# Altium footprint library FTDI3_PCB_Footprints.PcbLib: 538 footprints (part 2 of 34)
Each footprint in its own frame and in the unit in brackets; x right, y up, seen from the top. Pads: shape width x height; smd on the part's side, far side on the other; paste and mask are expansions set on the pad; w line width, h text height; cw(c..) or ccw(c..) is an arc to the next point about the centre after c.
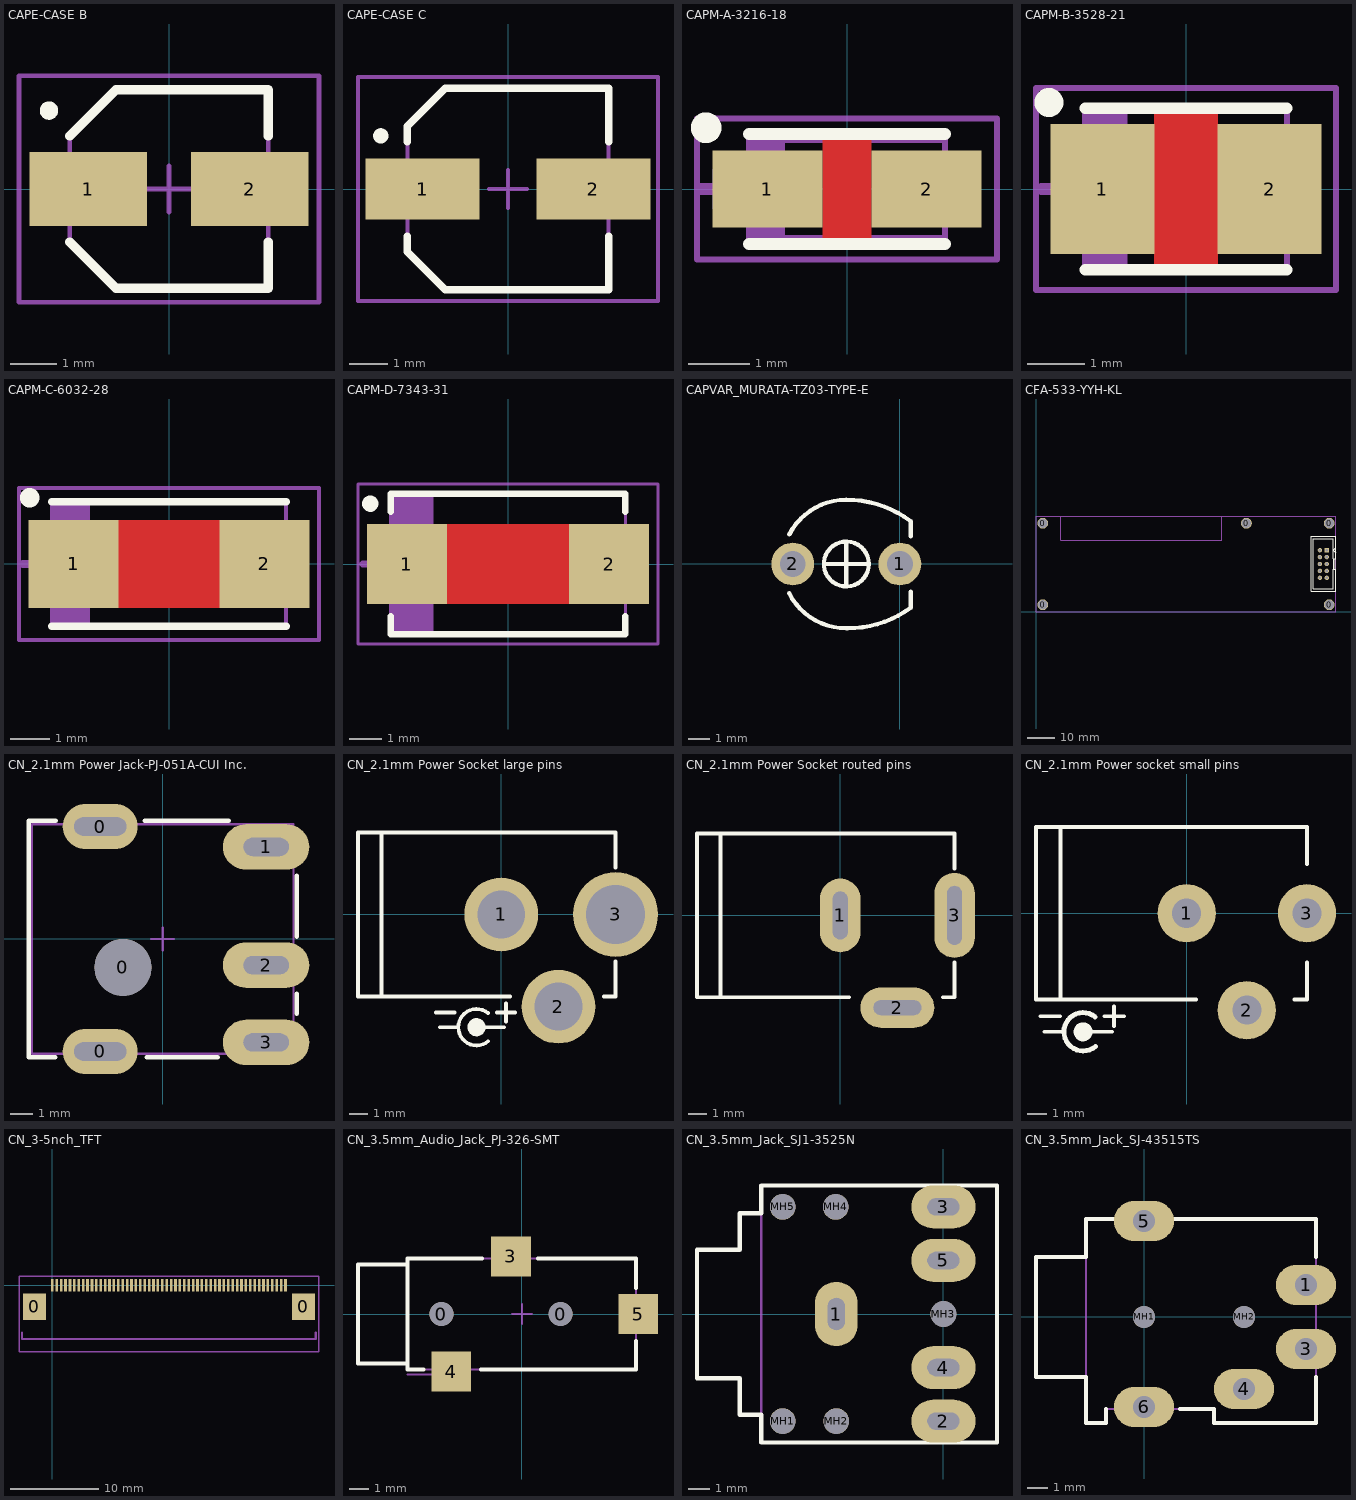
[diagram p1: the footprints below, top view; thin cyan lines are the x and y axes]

## CAPE-CASE B [mm] "Capacitor, aluminium electrolitytic; SMT, Case B"
pads (2):
  rect 2.55x1.6 smd: 1(-1.75,0) 2(1.75,0)
Top Overlay:
  circle w0.2: c-2.6,1.7 r0.1
  lines w0.2: -2.15,-1.15 -1.15,-2.15 2.15,-2.15 2.15,-1.15 ; -2.15,1.15 -1.15,2.15 2.15,2.15 2.15,1.15
M13_Assembly_Info:
  lines w0.1: -2.15,-1.15 -2.15,1.15 -1.15,2.15 2.15,2.15 2.15,-2.15 -1.15,-2.15 -2.15,-1.15
M15_Country_Yard:
  lines w0.1: -0.5,0 0.5,0 ; 0,-0.5 0,0.5 ; -3.25,-2.45 -3.25,2.45 3.25,2.45 3.25,-2.45 -3.25,-2.45
3D body: height 5.4, standoff 0, extent -2.3,-2.15 2.3,2.15

## CAPE-CASE C [mm] "Capacitor, aluminium electrolitytic; SMT, Case C"
pads (2):
  rect 3x1.6 smd: 1(-2.25,0) 2(2.25,0)
Top Overlay:
  circle w0.2: c-3.35,1.4 r0.1
  lines w0.2: -2.65,-1.25 -2.65,-1.65 -1.65,-2.65 2.65,-2.65 2.65,-1.25 ; -2.65,1.25 -2.65,1.65 -1.65,2.65 2.65,2.65 2.65,1.25
M13_Assembly_Info:
  lines w0.1: -2.65,-1.65 -1.65,-2.65 2.65,-2.65 2.65,2.65 -1.65,2.65 -2.65,1.65 -2.65,-1.65
M15_Country_Yard:
  lines w0.1: -0.5,0 0.5,0 ; 0,-0.5 0,0.5 ; -3.95,-2.95 3.95,-2.95 3.95,2.95 -3.95,2.95 -3.95,-2.95
3D body: height 5.41, standoff 0, extent -3,-2.625 2.9,2.675

## CAPM-A-3216-18 [mm] "Capacitor, SMT Tantalum; Body 3.2 x 1.6 mm (LxW typ)"
height 2.2
pads (2):
  rect 1.8x1.25 smd: 1(-1.3,0) 2(1.3,0)
Top Layer:
  pour cut-out: -0.4,0.9 0.4,0.9 0.4,-0.9 -0.4,-0.9
Top Overlay:
  circle w0.3: c-2.3,1 r0.1
  lines w0.2: -1.6,-0.9 1.6,-0.9 ; -1.6,0.9 1.6,0.9
M13_Assembly_Info:
  rectangle: -1.6,-0.8 -1.016,0.8
  lines w0.1: -1.6,-0.8 1.6,-0.8 1.6,0.8 -1.6,0.8 -1.6,-0.8
  lines w0.2: -2.4,0 -1.8,0 ; -2.1,-0.3 -2.1,0.3
M15_Country_Yard:
  lines w0.1: -0.35,0 0.35,0 ; 0,-0.35 0,0.35 ; -2.45,-1.15 2.45,-1.15 2.45,1.15 -2.45,1.15 -2.45,-1.15
3D body: height 1.8, standoff 0, extent -1.025,-0.8 1.6,0.8
3D body: height 1.8, standoff 0, extent -1.6,-0.8 -1.016,0.8

## CAPM-B-3528-21 [mm] "Capacitor, SMT Tantalum; Body 3.5 x 2.8 mm (LxW typ)"
height 2.5
pads (2):
  rect 1.8x2.25 smd: 1(-1.45,0) 2(1.45,0)
Top Layer:
  pour cut-out: -0.55,1.4 0.55,1.4 0.55,-1.4 -0.55,-1.4
Top Overlay:
  circle w0.3: c-2.375,1.5 r0.1
  lines w0.2: -1.75,-1.4 1.75,-1.4 ; -1.75,1.4 1.75,1.4
M13_Assembly_Info:
  rectangle: -1.75,-1.4 -1.016,1.4
  lines w0.1: -1.75,-1.4 -1.75,1.4 1.75,1.4 1.75,-1.4 -1.75,-1.4
  lines w0.2: -2.5,0 -1.9,0 ; -2.2,-0.3 -2.2,0.3
M15_Country_Yard:
  lines w0.1: -0.4,0 0.4,0 ; 0,-0.4 0,0.4 ; -2.6,-1.75 -2.6,1.75 2.6,1.75 2.6,-1.75 -2.6,-1.75
3D body: height 1.8, standoff 0, extent -1.75,-1.4 -1.166,1.4
3D body: height 1.8, standoff 0, extent -1.166,-1.4 1.75,1.4

## CAPM-C-6032-28 [mm] "Capacitor, SMT, Tantalum; Body 6.0 x 3.2 mm (LxW typ)"
height 3.4
pads (2):
  rect 2.3x2.25 smd: 1(-2.45,0) 2(2.45,0)
Top Layer:
  pour cut-out: -1.3,1.125 1.3,1.125 1.3,-1.125 -1.3,-1.125
Top Overlay:
  circle w0.3: c-3.575,1.7 r0.1
  lines w0.2: -3,-1.6 3,-1.6 ; -3,1.6 3,1.6
M13_Assembly_Info:
  rectangle: -3,-1.6 -2.032,1.6
  lines w0.1: -3,-1.6 -3,1.6 3,1.6 3,-1.6 -3,-1.6
  lines w0.2: -3.75,0 -3.15,0 ; -3.45,-0.3 -3.45,0.3
M15_Country_Yard:
  lines w0.1: -0.5,0 0.5,0 ; 0,-0.5 0,0.5 ; -3.85,-1.95 -3.85,1.95 3.85,1.95 3.85,-1.95 -3.85,-1.95
3D body: height 2.8, standoff 0, extent -3,-1.6 -2.425,1.6
3D body: height 2.8, standoff 0, extent -2.425,-1.6 3,1.6

## CAPM-D-7343-31 [mm] "Capacitor, SMT, Tantalum; Body 7.3 x 4.3 mm (LxW typ)"
height 3.7
pads (2):
  rect 2.45x2.45 smd: 1(-3.1,0) 2(3.1,0)
Top Layer:
  pour cut-out: -1.875,1.225 1.875,1.225 1.875,-1.225 -1.875,-1.225
Top Overlay:
  circle w0.3: c-4.225,1.85 r0.1
  lines w0.2: -3.6,-1.6 -3.6,-2.15 3.6,-2.15 3.6,-1.6 ; -3.6,1.6 -3.6,2.15 3.6,2.15 3.6,1.6
M13_Assembly_Info:
  rectangle: -3.6,-2.15 -2.286,2.15
  lines w0.1: -3.6,-2.15 -3.6,2.15 3.6,2.15 3.6,-2.15 -3.6,-2.15
  lines w0.2: -4.45,0 -3.85,0 ; -4.15,-0.3 -4.15,0.3
M15_Country_Yard:
  lines w0.1: -0.5,0 0.5,0 ; 0,-0.5 0,0.5 ; -4.6,-2.45 -4.6,2.45 4.6,2.45 4.6,-2.45 -4.6,-2.45
3D body: height 2.25, standoff 0.02, extent -3.65,-2.15 3.65,2.15

## CAPVAR_MURATA-TZ03-TYPE-E [mm] "MURATA TRIMMER CAP TZ03 SERIES - E TYPE"
height 4.8
pads (2):
  round 2 hole 1.2: 1(0,0) 2(-5,0)
Top Overlay:
  circle w0.2: c-2.5,0 r1.05
  lines w0.2: -5.169,-1.371 ccw(c-2.5,0) -2.5,-3.001 ; -5.158,1.391 cw(c-2.5,0) -2.5,3 cw(c-2.5,-2) 0.5,2 0.5,1.3 ; -3.5,0 -1.5,0 ; -2.5,-1 -2.5,1 ; -2.439,-3 ccw(c-2.439,2) 0.5,-2.045 ; 0.5,-2 0.5,-1.3
3D body: height 4.82, standoff -3.28, extent -5.45,-3 0.55,3

## CFA-533-YYH-KL [mm] "LED Display Module"
pads (15):
  round 4 hole 3.5: 0(2.5,2.5) 0(2.5,32.5) 0(77.5,32.5) 0(108,2.5) 0(108,32.5)
  rect 1.6x1.6 hole 1: 1(107.1,22.58)
  round 1.6 hole 1: 2(104.56,22.58) 3(107.1,20.04) 4(104.56,20.04) 5(107.1,17.5) 6(104.56,17.5) 7(107.1,14.96) 8(104.56,14.96) 9(107.1,12.42) 10(104.56,12.42)
Top Overlay:
  lines w0.2: 109.6,15.52 109.6,19.52 ; 110.2,15.52 110.2,19.52 ; 110.4,21.575 109.4,22.575 110.4,23.575 ; 101.3,7.42 101.3,27.72 110.4,27.72 110.4,19.52 109.4,19.52 109.4,26.72 102.2,26.72 102.2,8.32 109.4,8.32 109.4,15.52 110.4,15.52 110.4,7.42 101.3,7.42
M13_Assembly_Info:
  lines w0.4: 9.125,34.825 9.125,26.25 68.5,26.25 68.5,34.825 ; 0,0 110.5,0 110.5,35 0,35 0,0

## CN_2.1mm Power Jack-PJ-051A-CUI Inc. [mm] "2.1mm Power Jack; DK cat.No. CP-051A-ND; CUI Inc. PJ-051A"
height 11
pads (6):
  oval 3.3x2 hole 0.8 slot 2.3 at 0 deg: 0(-2.75,-4.95) 0(-2.75,4.95)
  round 2.5 hole 2.5 unplated: 0(-1.75,-1.25)
  oval 3.8x2 hole 0.8 slot 2 at 0 deg: 1(4.55,4.05) 2(4.55,-1.15) 3(4.55,-4.55)
Top Overlay:
  lines w0.2: -4.73,-5.2 -5.9,-5.2 -5.9,5.2 -4.7,5.2 ; -0.8,5.2 2.9,5.2 ; -0.7,-5.2 2.42,-5.2 ; 5.9,-3.29 5.9,-2.4 ; 5.9,0.11 5.9,2.78
M13_Assembly_Info:
  lines w0.1: -5.75,-5.05 -5.75,5.05 5.75,5.05 5.75,-5.05 -5.75,-5.05
M15_Country_Yard:
  lines w0.1: -0.5,0 0.5,0 ; 0,-0.5 0,0.5
3D body: height 7.32, standoff -2.48, extent -5.755,-4.99 5.995,5.11

## CN_2.1mm Power Socket large pins [mm] "2.1mm Power Jack; DK cat.No. CP-002A-ND; CUI Inc. PJ-002A"
pads (3):
  round 4 hole 2.6: 1(0,0) 2(3.1,-5)
  round 4.6 hole 3.2: 3(6.2,0)
Top Overlay:
  circle w0.5: c-1.34,-6.115 r0.24
  lines w0.2: -6.5,-4.445 -6.5,4.445 ; -3.54,-5.315 -2.54,-5.315 ; -3.34,-6.115 -2.34,-6.115 ; -1.1,-6.115 0.16,-6.115 ; -0.719,-5.344 ccw(c-1.34,-6.115) -0.702,-6.872 ; -0.24,-5.315 0.76,-5.315 ; 0.26,-5.815 0.26,-4.815 ; 0.485,-4.445 -7.77,-4.445 -7.77,4.445 6.2,4.445 6.2,2.54 ; 5.565,-4.445 6.2,-4.445 6.2,-2.54
M13_Assembly_Info:
  lines w0.1: 0.485,-4.445 -7.77,-4.445 -7.77,4.445 6.2,4.445 6.2,2.54 ; 5.565,-4.445 6.2,-4.445 6.2,-2.54
3D body: height 0, standoff 0, extent -7.77,-4.445 6.2,4.445

## CN_2.1mm Power Socket routed pins [mm] "2.1mm Power Jack; DK cat.No. CP-002A-ND; CUI Inc. PJ-002A"
height 11
pads (3):
  oval 2.2x4 hole 0.8 slot 2.6 at 90 deg: 1(0,0)
  oval 4x2.2 hole 0.8 slot 2.6 at 0 deg: 2(3.1,-5)
  oval 2.2x4.6 hole 0.8 slot 3.2 at 90 deg: 3(6.2,0)
Top Overlay:
  lines w0.2: -6.5,-4.445 -6.5,4.445 ; 0.485,-4.445 -7.77,-4.445 -7.77,4.445 6.2,4.445 6.2,2.54 ; 5.565,-4.445 6.2,-4.445 6.2,-2.54
M13_Assembly_Info:
  lines w0.1: 0.485,-4.445 -7.77,-4.445 -7.77,4.445 6.2,4.445 6.2,2.54 ; 5.565,-4.445 6.2,-4.445 6.2,-2.54
3D body: height 11.02, standoff -3.48, extent -7.64,-5.09 6.76,4.31

## CN_2.1mm Power socket small pins [mm] "2.1mm Power Jack; DK cat.No. CP-102A-ND; CUI Inc. PJ-102A"
pads (3):
  round 3 hole 1.5: 1(0,0) 2(3.1,-5) 3(6.2,0)
Top Overlay:
  circle w0.5: c-5.34,-6.115 r0.24
  lines w0.2: -7.54,-5.315 -6.54,-5.315 ; -7.34,-6.115 -6.34,-6.115 ; -6.5,-4.445 -6.5,4.445 ; -5.1,-6.115 -3.84,-6.115 ; -4.24,-5.315 -3.24,-5.315 ; -3.74,-5.815 -3.74,-4.815 ; 0.485,-4.445 -7.77,-4.445 -7.77,4.445 6.2,4.445 6.2,2.54 ; 5.565,-4.445 6.2,-4.445 6.2,-2.54
  lines w0.254: -4.719,-5.344 ccw(c-5.34,-6.115) -4.702,-6.872
M13_Assembly_Info:
  lines w0.1: 0.485,-4.445 -7.77,-4.445 -7.77,4.445 6.2,4.445 6.2,2.54 ; 5.565,-4.445 6.2,-4.445 6.2,-2.54
3D body: height 0, standoff 0, extent -7.77,-4.445 6.2,4.445

## CN_3-5nch_TFT [mm] "Connector for 3.5\" touch screens"
pads (56):
  rect 2.6x3 smd: 0(-2.04,-2.425) 0(28.54,-2.425)
  rect 0.3x1.45 smd: 1(0,0) 2(0.5,0) 3(1,0) 4(1.5,0) 5(2,0) 6(2.5,0) 7(3,0) 8(3.5,0) 9(4,0) 10(4.5,0) 11(5,0) 12(5.5,0) 13(6,0) 14(6.5,0) 15(7,0) 16(7.5,0) 17(8,0) 18(8.5,0) 19(9,0) 20(9.5,0) 21(10,0) 22(10.5,0) 23(11,0) 24(11.5,0) 25(12,0) 26(12.5,0) 27(13,0) 28(13.5,0) 29(14,0) 30(14.5,0) 31(15,0) 32(15.5,0) 33(16,0) 34(16.5,0) 35(17,0) 36(17.5,0) 37(18,0) 38(18.5,0) 39(19,0) 40(19.5,0) 41(20,0) 42(20.5,0) 43(21,0) 44(21.5,0) 45(22,0) 46(22.5,0) 47(23,0) 48(23.5,0) 49(24,0) 50(24.5,0) 51(25,0) 52(25.5,0) 53(26,0) 54(26.5,0)
M13_Assembly_Info:
  lines w0.254: -3.45,-5.37 -3.45,-6.1 29.95,-6.1 29.95,-5.37
M15_Country_Yard:
  lines w0.15: 30.28,1.04 -3.79,1.04 -3.79,-7.58 30.31,-7.58 30.31,1.04
3D body: height 2, standoff 0, extent -3.2,-5.35 29.5,-4
3D body: height 2, standoff 0, extent -2.45,-4.025 28.85,-0.85

## CN_3.5mm_Audio_Jack_PJ-326-SMT [mm] "SJ-3523-SMT Audio Jack, 3.5mm, SMT, Huayipeng Electronics Co.."
height 5
pads (5):
  round 1.2 hole 1.2 unplated: 0(-4.05,0) 0(1.95,0)
  rect 2x2 smd: 3(-0.55,2.9) 4(-3.55,-2.9) 5(5.85,0)
Top Overlay:
  lines w0.2: -5.75,-2.5 -8.25,-2.5 -8.25,2.5 -5.75,2.5 ; -4.95,-2.8 -5.75,-2.8 -5.75,2.8 -2,2.8 ; -2.05,-2.8 5.75,-2.8 5.75,-1.36 ; 0.8,2.8 5.75,2.8 5.75,1.31
M13_Assembly_Info:
  lines w0.1: -5.75,-3.05 -3.55,-3.05 ; -5.75,-2.5 -8.25,-2.5 -8.25,2.5 -5.75,2.5 ; -5.75,-2.8 5.75,-2.8 5.75,2.8 -5.75,2.8 -5.75,-2.8
M15_Country_Yard:
  lines w0.1: -0.5,0 0.5,0 ; 0,-0.5 0,0.5
3D body: height 5, standoff 0, extent -5.75,-2.8 5.75,2.8

## CN_3.5mm_Jack_SJ1-3525N [mm] "3.5mm AUDIO JACK STEREO"
pads (10):
  oval 2x3 hole 0.8 slot 1.5 at 90 deg: 1(-5,0)
  oval 3x2 hole 0.8 slot 1.5 at 0 deg: 2(0,-5) 3(0,5) 4(0,-2.5) 5(0,2.5)
  round 1.2 hole 1.2 unplated: MH1(-7.5,-5) MH2(-5,-5) MH3(0,0) MH4(-5.025,5) MH5(-7.5,5)
Top Overlay:
  lines w0.2: -11.5,-3 -11.5,3 -9.5,3 -9.5,4.7 -8.5,4.7 -8.5,6 2.5,6 2.5,-6 -8.5,-6 -8.5,-4.7 -9.5,-4.7 -9.5,-3 -11.5,-3
M13_Assembly_Info:
  lines w0.1: -8.5,-4.7 -9.5,-4.7 -9.5,-3 -11.5,-3 -11.5,3 -9.5,3 -9.5,4.7 -8.5,4.7 ; -8.5,-4.7 -8.5,4.7 ; -8.5,-4.7 -8.5,-6 2.5,-6 2.5,6 -8.5,6 -8.5,4.7
3D body: height 5.52, standoff -3.28, extent -11.65,-6 2.35,6

## CN_3.5mm_Jack_SJ-43515TS [mm] "3.5mm Audio Jack; four contacts; one switch"
height 5
pads (7):
  oval 3x2 hole 1.1: 1(8.1,1.6) 3(8.1,-1.6) 4(5,-3.6) 5(0,4.8) 6(0,-4.5)
  round 1.1 hole 1.1 unplated: MH1(0,0) MH2(5,0)
Top Overlay:
  lines w0.2: -1.9,-4.6 -1.9,-5.3 -2.9,-5.3 -2.9,-3 -5.4,-3 -5.4,3 -2.9,3 -2.9,4.9 8.6,4.9 8.6,3 ; 1.8,-4.6 3.5,-4.6 3.5,-5.3 8.6,-5.3 8.6,-3
M13_Assembly_Info:
  lines w0.1: -2.9,-4.575 -2.9,4.9 8.6,4.9 8.6,-5.3 3.5,-5.3 3.5,-4.6 -1.9,-4.6 -1.9,-5.3 -2.9,-5.3 -2.9,-3 -5.4,-3 -5.4,3 -2.9,3 -2.9,4.7
3D body: height 5.52, standoff -3.28, extent -5.4,-5.9 8.6,6.1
